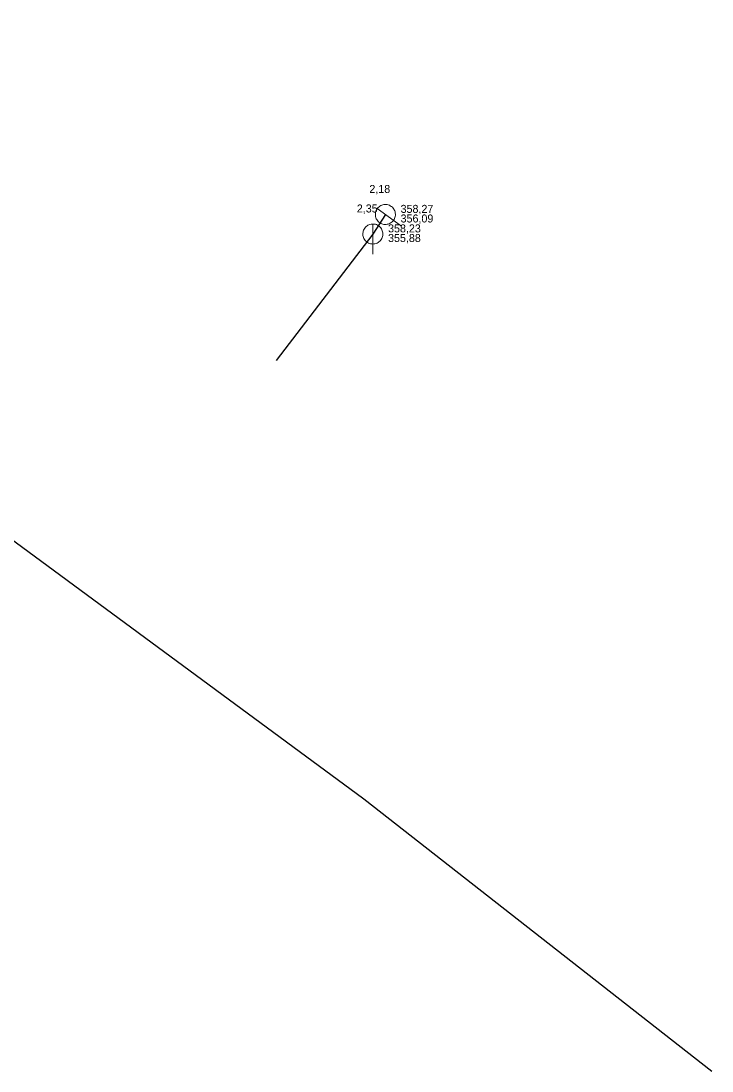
# Model space of a CAD drawing. Extents: x -809028 to -807737, y -990545 to -989489.
# Drawn here: x -808552.3 to -808483.2, y -990338.7 to -990233.7 of the extents above; entities that cross this region are included whole.
import ezdxf

# ---------------------------------------------------------------- set-up
doc = ezdxf.new("R2010")
doc.units = 0
doc.header["$LTSCALE"] = 0.32
for name, color, linetype, lineweight in [('1', 7, 'Continuous', 13), ('14', 7, 'Continuous', 25), ('17', 7, 'Continuous', 25), ('22', 7, 'Continuous', 13)]:
    doc.layers.add(name, color=color, linetype=linetype, lineweight=lineweight)

msp = doc.modelspace()

# ---------------------------------------------------------------- linework, layer by layer
at = {"layer": '14'}
for p, q in [((-808515.878, -990253.071), (-808517.131, -990255.023)), ((-808517.131, -990255.023), (-808526.806, -990267.671))]:
    msp.add_line(p, q, dxfattribs=at)
at = {"layer": '17'}
msp.add_lwpolyline([(-808650.485, -990233.727), (-808578.848, -990266.883), (-808559.725, -990280.603), (-808555.451, -990283.938), (-808518.015, -990311.482), (-808483.239, -990338.707)], dxfattribs=at)
at = {"layer": '22'}
for p, q in [((-808514.255, -990254.241), (-808516.688, -990252.486)), ((-808517.131, -990257.023), (-808517.13, -990254.023))]:
    msp.add_line(p, q, dxfattribs=at)
for points in [[(-808515.292, -990252.26), (-808515.384, -990252.201), (-808515.482, -990252.152), (-808515.586, -990252.115), (-808515.691, -990252.088), (-808515.8, -990252.073), (-808515.909, -990252.071), (-808516.019, -990252.081), (-808516.126, -990252.102), (-808516.231, -990252.135), (-808516.33, -990252.179), (-808516.425, -990252.234), (-808516.513, -990252.3), (-808516.594, -990252.374), (-808516.666, -990252.456), (-808516.728, -990252.547), (-808516.78, -990252.643), (-808516.823, -990252.744), (-808516.853, -990252.849), (-808516.87, -990252.957), (-808516.877, -990253.066), (-808516.871, -990253.176), (-808516.854, -990253.284), (-808516.825, -990253.39), (-808516.785, -990253.491), (-808516.733, -990253.588), (-808516.671, -990253.678), (-808516.6, -990253.762), (-808516.52, -990253.836), (-808516.432, -990253.902), (-808516.338, -990253.958), (-808516.239, -990254.003), (-808516.135, -990254.037), (-808516.028, -990254.059), (-808515.919, -990254.07), (-808515.809, -990254.068), (-808515.7, -990254.055), (-808515.593, -990254.03), (-808515.491, -990253.993), (-808515.392, -990253.946), (-808515.299, -990253.887), (-808515.214, -990253.819), (-808515.136, -990253.742), (-808515.067, -990253.657), (-808515.008, -990253.565), (-808514.959, -990253.466), (-808514.921, -990253.364), (-808514.895, -990253.258), (-808514.88, -990253.149), (-808514.878, -990253.039), (-808514.887, -990252.93), (-808514.908, -990252.823), (-808514.941, -990252.719), (-808514.985, -990252.618), (-808515.04, -990252.524), (-808515.105, -990252.436), (-808515.179, -990252.355), (-808515.262, -990252.283)], [(-808516.131, -990255.023), (-808516.136, -990254.914), (-808516.154, -990254.806), (-808516.184, -990254.7), (-808516.224, -990254.599), (-808516.276, -990254.502), (-808516.338, -990254.412), (-808516.41, -990254.329), (-808516.49, -990254.255), (-808516.578, -990254.189), (-808516.672, -990254.134), (-808516.772, -990254.089), (-808516.877, -990254.056), (-808516.984, -990254.034), (-808517.093, -990254.024), (-808517.203, -990254.026), (-808517.311, -990254.04), (-808517.418, -990254.065), (-808517.521, -990254.102), (-808517.619, -990254.151), (-808517.711, -990254.209), (-808517.797, -990254.278), (-808517.874, -990254.355), (-808517.943, -990254.441), (-808518.002, -990254.533), (-808518.05, -990254.631), (-808518.087, -990254.734), (-808518.113, -990254.841), (-808518.127, -990254.949), (-808518.13, -990255.059), (-808518.12, -990255.168), (-808518.099, -990255.275), (-808518.065, -990255.379), (-808518.021, -990255.479), (-808517.966, -990255.574), (-808517.9, -990255.662), (-808517.826, -990255.742), (-808517.743, -990255.814), (-808517.653, -990255.876), (-808517.557, -990255.928), (-808517.455, -990255.969), (-808517.35, -990255.999), (-808517.242, -990256.017), (-808517.132, -990256.023), (-808517.023, -990256.017), (-808516.915, -990255.999), (-808516.81, -990255.97), (-808516.708, -990255.929), (-808516.611, -990255.877), (-808516.521, -990255.815), (-808516.438, -990255.744), (-808516.363, -990255.664), (-808516.298, -990255.576), (-808516.242, -990255.482), (-808516.198, -990255.382), (-808516.164, -990255.278), (-808516.142, -990255.17), (-808516.132, -990255.061)]]:
    msp.add_lwpolyline(points, close=True, dxfattribs=at)

# ---------------------------------------------------------------- texts
at = {"layer": '1'}
for s, p in [('2,18', (-808517.478, -990250.919)), ('2,35', (-808518.731, -990252.871))]:
    msp.add_text(s, height=0.8, dxfattribs=at).set_placement(p)
at = {"layer": '14'}
for s, p in [('358,27', (-808514.356, -990252.911)), ('356,09', (-808514.356, -990253.871)), ('358,23', (-808515.609, -990254.863)), ('355,88', (-808515.609, -990255.823))]:
    msp.add_text(s, height=0.8, dxfattribs=at).set_placement(p)

doc.saveas('drawing.dxf')
